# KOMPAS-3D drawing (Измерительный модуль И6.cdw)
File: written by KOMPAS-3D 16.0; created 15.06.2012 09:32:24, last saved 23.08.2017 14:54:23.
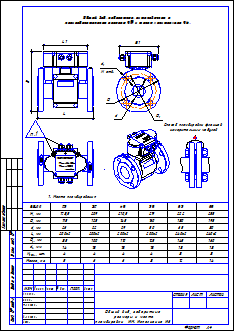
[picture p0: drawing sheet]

Sheet 1: A4, portrait

Title block, sheet 1: sheets: 29; sheet format: A4; stored path: D:\Общее для проектов\Шаблон проекта\5-ти трубная система\5-х трубная шаблон.cdw; cell 51: МО, Воскресенсикй р-н, п. Хорлово, ул. Интернациональная, д. 4

Views: Вид 2, Вид 3
Referenced files in C:\Program Files (x86)\ASCON\KOMPAS-3D V16\Sys\: spds.lcs, EngSys.lcs, GRAPHIC.LHS
Referenced files: graphic.tdp
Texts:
  Смирнов В.С.
  УУ-3423
  GOST Common
  Normal
  List Paragraph
  heading 3
  для схемы
  txt
  Т0-элементы
  Ду,мм
  Н, мм
  D, мм
  d, мм
  L, мм
  Масса, кг
  N отв.
  Сделано в России
  Тmax= 150 C
  ИНТЕЛПРИБОР
  Общий вид, габаритные, установочные и
  присоединительные размеры ИМ с типом конструкции И6.
  1. Место пломбирования
  Способ пломбировки фланцев
  измерительных модулей
  Размеры, параметризация
  сит. план
  подача ГВС
  обратка ГВС
  хвс
  обратка
  POLYLINE_STYLE_0.25_RGB_0_0_0
  стены
  Основная (не является границей для штриховки)
  POLYLINE_STYLE_0.18_RGB_0_0_0
  ХВС
  зеленая
  Красная тонкая
  арматура
  Подача
  Скрытая линия
  Ось Z
  Ось Y
  Ось X
  Образующая трубопровода (проектируемого)
  Трубопровод толщиной 0.6мм (одна линия)
  Трубопровод толщиной 1.2мм (одна линия)
  Трубопровод толщиной 1.0мм (одна линия)
  Трубопровод толщиной 0.8мм (одна линия)
  Трубопровод существующий (одна линия)
  Трубопровод невидимый (одна линия)
  Трубопровод демонтируемый (одна линия)
  Осевая трубопровода
  Осевая трубопровода (демонтируемого)
  Образующая трубопровода (существующего)
  Образующая трубопровода (невидимого)
  Изолированный трубопровод проектируемый (одна линия)
  Изолированный трубопровод существующий (одна линия)
  Образующая изоляции
  Изоляция
  Изолированный трубопровод невидимый (одна линия)
  Штрих пвс 075
  штрих пвс 2,5
  существующее оборудование
  Существующее оборудование
  K5LT_BASIC_RGB_0_0_255_THICK_0.53
  POLYLINE_STYLE_1.51_RGB_0_0_255
  POLYLINE_STYLE_0.50_RGB_128_128_128
  K5LT_AXLED_RGB_255_128_0_SC_1_THICK_0.18
  ACAD_ISO04W100_RGB_0_0_0_SC_1_THICK_0.18
  тонкая черная
  тонкая красная
  тонкая синяя
  тонкая оранж
  красн штрих
  пломбировка
  Провода
  синий штрих
  Стили документа
  G2co
  расход вторичной воды объемный
  расход вторичной воды объемный при 70гр
  Gco
  расход теплоносителя массовый
  расход теплоносит объемн подающ
  расход теплоносит объемн обр
  Лапир
  Ghvs
  Im1
  Im2
  Im3
  Im4
  Im5
  Khvs
  норматив ХВС
  число подъездов
  число этажей
  Nkv
  число квартир
  тепловая нагрузка на отопление
  сумма Q
  Qgvs
  тепловая нагрузка ГВС
  тепловая нагрузка на циркуляцию ГВС
  иммитовставка или под манометр
  ro1
  ro2
  ro3
  ro4
  верх предел темп граф
  нижн предел темп граф
  темп подачи ГВС
  темп обр ГВС
  темр хол воды
  vzdh
  Kchn
  Ktp
  Knp
  tnv
  Vклап
  KLP
  RPD
  RDS
  PUMP
  ro5
  beta
  tnv98
  Shifr
  Переход ГОСТ 17378-2001
  Переход
  ГОСТ
  Сталь 09Г2С ГОСТ 19281-89
  Втулка 20x50
  Лит-Масса-Масштаб
  Материал-Предприятие
  Title Specification
  Body Specification ( left align )
  Body Specificaton ( centered )
  Поз.
  Кол.
  Приме-
  чание
  Таблица спецификации
  Засыпка
  Штрих3
  Штрих2
  Штрих1
  Песок
  Штр0.5пр7
  Штр0.5пр12
  Штр0.3пр10
  Штр1.4пр21.21
  Штр1пр15
  Штр2.12пр35
  Штр1.5пр25
  Штр2.82пр42.42
  Штр2пр30
  SACNCR_ISO 1
  Электрощитовая
  Пр-1
  Ок-1
  Обозначение стандарта
  Типоразмер
  Пояснительная записка
  Разраб.
  Пров.
  Т.контр.
  Н.контр.
  Утв.
  Общий вид, габаритные
  размеры и места
  пломбировки  ИМ. Исполнение И6
  Рабочие чертежи основного комплекта. ГОСТ Р 21.1101-2009 Ф3
  Стадия
  Лист
  Листов
  Изм.
  Кол.уч.
  №док.
  Подп.
  Дата
  Изменение
  Номер документа
  Подпись
  Наименование объекта строительства, в состав которого входит здание, наим. микр
  Наименование здания (сооружения)
  Порядковый номер листа
  Количество листов в документе
  Наименование изображения
  Индекс предприятия, выпускающего документ
  Инв. № подл.
  Подп. и дата
  Взам. инв. №
  Инвентарный номер подлинника
  Подпись принявшего подлинник на хранение
  Инвентарный номер подлинника, взамен которого выпущен данный подлинник
  Согласовано
  Формат листа
  Согласование
  03 Рабочие чертежи основного комплекта. ГОСТ Р 21.1101-2009 Ф3
Dimensions and other numbers on the sheet: 25; 32; 40; 50; 65; 80; 178,5; 115; 26; 200 3; 85; 14; 4; 5; 209; 135; 100; 18; 6; 210,5; 145; 39; 110; 219; 160; 125; 8; 232; 180; 240 3; 12; 255; 195; 09Г2С; 1; 20; 29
